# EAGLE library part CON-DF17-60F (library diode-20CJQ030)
Hirose DF17 series 0.5mm pitch 60pin female connector
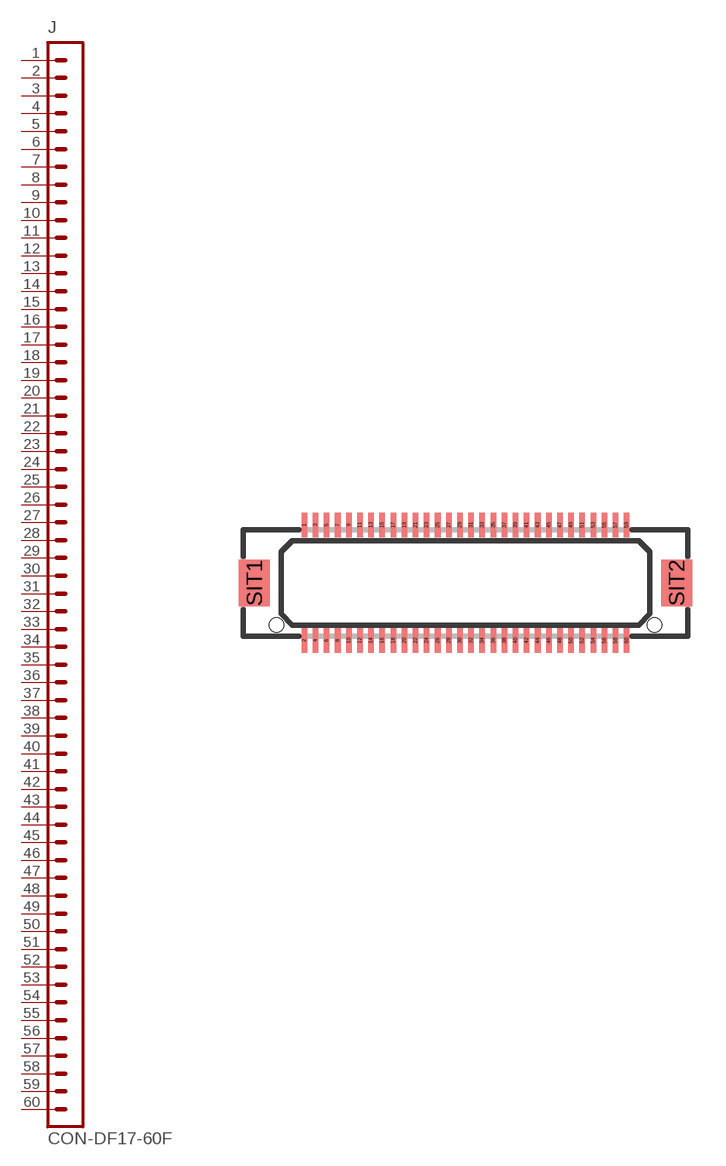
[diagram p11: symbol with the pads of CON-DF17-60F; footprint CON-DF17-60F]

Designator prefix J

## CON-DF17-60F  [CON-DF17-60F]
1  1  pas
2  2  pas
3  3  pas
4  4  pas
5  5  pas
6  6  pas
7  7  pas
8  8  pas
9  9  pas
10  10  pas
11  11  pas
12  12  pas
13  13  pas
14  14  pas
15  15  pas
16  16  pas
17  17  pas
18  18  pas
19  19  pas
20  20  pas
21  21  pas
22  22  pas
23  23  pas
24  24  pas
25  25  pas
26  26  pas
27  27  pas
28  28  pas
29  29  pas
30  30  pas
31  31  pas
32  32  pas
33  33  pas
34  34  pas
35  35  pas
36  36  pas
37  37  pas
38  38  pas
39  39  pas
40  40  pas
41  41  pas
42  42  pas
43  43  pas
44  44  pas
45  45  pas
46  46  pas
47  47  pas
48  48  pas
49  49  pas
50  50  pas
51  51  pas
52  52  pas
53  53  pas
54  54  pas
55  55  pas
56  56  pas
57  57  pas
58  58  pas
59  59  pas
60  60  pas

## Footprint CON-DF17-60F (pad centres in mm)
Hirose DF17 60pin 0.5mm pitch receptacle
smd 0.25 x 1.1: 1 -7.25,2.6; 2 -7.25,-2.6; 3 -6.75,2.6; 4 -6.75,-2.6; 5 -6.25,2.6; 6 -6.25,-2.6; 7 -5.75,2.6; 8 -5.75,-2.6; 9 -5.25,2.6; 10 -5.25,-2.6; 11 -4.75,2.6; 12 -4.75,-2.6; 13 -4.25,2.6; 14 -4.25,-2.6; 15 -3.75,2.6; 16 -3.75,-2.6; 17 -3.25,2.6; 18 -3.25,-2.6; 19 -2.75,2.6; 20 -2.75,-2.6; 21 -2.25,2.6; 22 -2.25,-2.6; 23 -1.75,2.6; 24 -1.75,-2.6; 25 -1.25,2.6; 26 -1.25,-2.6; 27 -0.75,2.6; 28 -0.75,-2.6; 29 -0.25,2.6; 30 -0.25,-2.6; 31 0.25,2.6; 32 0.25,-2.6; 33 0.75,2.6; 34 0.75,-2.6; 35 1.25,2.6; 36 1.25,-2.6; 37 1.75,2.6; 38 1.75,-2.6; 39 2.25,2.6; 40 2.25,-2.6; 41 2.75,2.6; 42 2.75,-2.6; 43 3.25,2.6; 44 3.25,-2.6; 45 3.75,2.6; 46 3.75,-2.6; 47 4.25,2.6; 48 4.25,-2.6; 49 4.75,2.6; 50 4.75,-2.6; 51 5.25,2.6; 52 5.25,-2.6; 53 5.75,2.6; 54 5.75,-2.6; 55 6.25,2.6; 56 6.25,-2.6; 57 6.75,2.6; 58 6.75,-2.6; 59 7.25,2.6; 60 7.25,-2.6
smd 1.4 x 2.1: SIT1 -9.5,0; SIT2 9.5,0
hole 0.65 at -8.5,-1.9
hole 0.65 at 8.5,-1.9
